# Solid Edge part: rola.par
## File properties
Author: ion
Template: Iso Part.par
Last saved by: ion
Revision: 1
Application: Solid Edge
Accuracy: 0,990
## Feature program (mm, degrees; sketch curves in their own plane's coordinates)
sketch for "unnamed Protrusion 1" plane through (0, 0, 0) normal (0, -1, 0) x-axis (1, 0, 0)
  circle centre (0, 0) radius 5
extrude "unnamed Protrusion 1" add finite 30 along -normal
fillet "Round_1" radius 5
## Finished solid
Body 1: solid body, 3 faces, 2 edges, 0 vertices.
  Faces by surface: cylinder 1, plane 1, sphere 1
  Edges by curve: circle 2
Bounding box of the edges (mm; curved faces can reach further): 10.000 x 25.000 x 10.000, from (-5, 5, -5) to (5, 30, 5).
Cylindrical faces by radius (mm): R5 x1
Spherical faces by radius (mm): R5 x1
Planar faces by outward normal: +y 1
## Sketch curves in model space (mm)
circle centre (0, 0, 0) radius 5
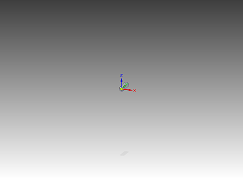
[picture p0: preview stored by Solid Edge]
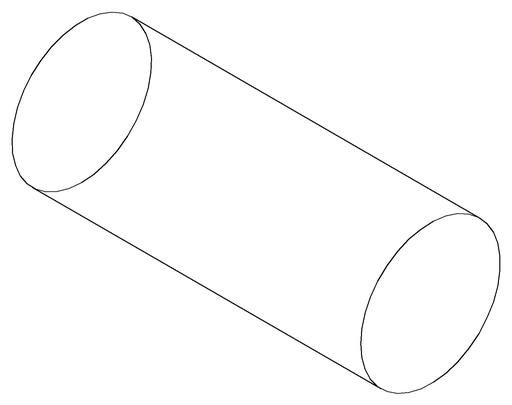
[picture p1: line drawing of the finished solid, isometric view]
